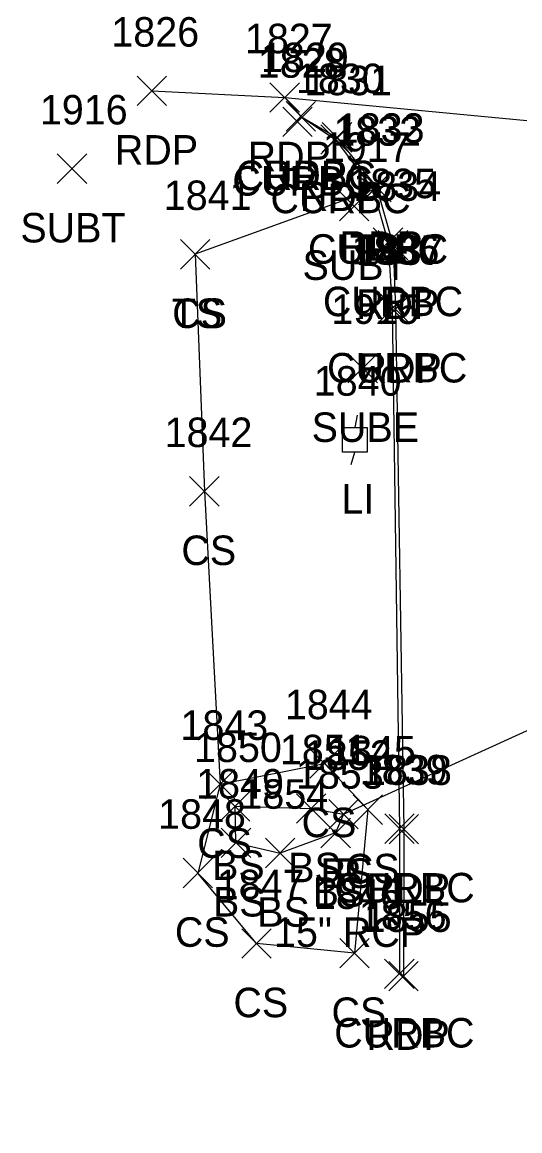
# Model space of a CAD drawing. Extents: x 1462089 to 1464015, y 730534 to 736144.
# Drawn here: x 1462879.2 to 1462912.9, y 734929.7 to 735004.8 of the extents above; entities that cross this region are included whole.
import ezdxf

# ---------------------------------------------------------------- set-up
doc = ezdxf.new("R2010")
doc.units = 0
for name, color, linetype in [('D_A', 7, 'Continuous'), ('D_C', 7, 'Continuous'), ('D_I', 7, 'Continuous'), ('D_TIC', 7, 'Continuous'), ('DCP', 7, 'Continuous'), ('L_A', 7, 'Continuous'), ('L_I', 7, 'Continuous'), ('L_TIC', 7, 'Continuous'), ('LELB', 7, 'Continuous'), ('P_A', 7, 'Continuous'), ('P_I', 7, 'Continuous'), ('P_TIC', 7, 'Continuous'), ('PET', 7, 'Continuous'), ('R_A', 7, 'Continuous'), ('R_I', 7, 'Continuous'), ('R_TIC', 7, 'Continuous'), ('RC', 7, 'Continuous'), ('U_A', 7, 'Continuous'), ('U_I', 7, 'Continuous'), ('U_TIC', 7, 'Continuous'), ('ULP', 7, 'Continuous')]:
    doc.layers.add(name, color=color, linetype=linetype)

msp = doc.modelspace()

# ---------------------------------------------------------------- linework, layer by layer
at = {"layer": 'D_TIC'}
for points in [[(1462899.982, 734950.137), (1462901.982, 734952.137)], [(1462901.982, 734950.137), (1462899.982, 734952.137)]]:
    msp.add_lwpolyline(points, dxfattribs=at)
at = {"layer": 'DCP'}
msp.add_lwpolyline([(1462900.982, 734951.137), (1462945.828, 734971.561)], dxfattribs=at)
at = {"layer": 'L_TIC'}
for points in [[(1462901.983, 734992.46), (1462903.983, 734994.46)], [(1462903.983, 734992.46), (1462901.983, 734994.46)], [(1462889.919, 734988.102), (1462891.919, 734990.102)], [(1462891.919, 734988.102), (1462889.919, 734990.102)], [(1462889.919, 734988.102), (1462891.919, 734990.102)], [(1462891.919, 734988.102), (1462889.919, 734990.102)], [(1462890.542, 734972.031), (1462892.542, 734974.031)], [(1462892.542, 734972.031), (1462890.542, 734974.031)], [(1462898.695, 734953.579), (1462900.695, 734955.579)], [(1462900.695, 734953.579), (1462898.695, 734955.579)], [(1462891.616, 734952.175), (1462893.616, 734954.175)], [(1462893.616, 734952.175), (1462891.616, 734954.175)], [(1462891.616, 734952.175), (1462893.616, 734954.175)], [(1462893.616, 734952.175), (1462891.616, 734954.175)], [(1462892.625, 734950.673), (1462894.625, 734952.673)], [(1462894.625, 734950.673), (1462892.625, 734952.673)], [(1462897.789, 734950.522), (1462899.789, 734952.522)], [(1462899.789, 734950.522), (1462897.789, 734952.522)], [(1462899.982, 734950.137), (1462901.982, 734952.137)], [(1462901.982, 734950.137), (1462899.982, 734952.137)], [(1462901.625, 734950.448), (1462903.625, 734952.448)], [(1462903.625, 734950.448), (1462901.625, 734952.448)], [(1462899.442, 734948.866), (1462901.442, 734950.866)], [(1462901.442, 734948.866), (1462899.442, 734950.866)], [(1462892.686, 734948.2), (1462894.686, 734950.2)], [(1462894.686, 734948.2), (1462892.686, 734950.2)], [(1462892.686, 734948.2), (1462894.686, 734950.2)], [(1462894.686, 734948.2), (1462892.686, 734950.2)], [(1462895.681, 734947.505), (1462897.681, 734949.505)], [(1462897.681, 734947.505), (1462895.681, 734949.505)], [(1462895.681, 734947.505), (1462897.681, 734949.505)], [(1462897.681, 734947.505), (1462895.681, 734949.505)], [(1462890.103, 734946.147), (1462892.103, 734948.147)], [(1462892.103, 734946.147), (1462890.103, 734948.147)], [(1462890.103, 734946.147), (1462892.103, 734948.147)], [(1462892.103, 734946.147), (1462890.103, 734948.147)], [(1462894.073, 734941.372), (1462896.073, 734943.372)], [(1462896.073, 734941.372), (1462894.073, 734943.372)], [(1462900.722, 734940.712), (1462902.722, 734942.712)], [(1462902.722, 734940.712), (1462900.722, 734942.712)]]:
    msp.add_lwpolyline(points, dxfattribs=at)
at = {"layer": 'LELB'}
for points in [[(1462902.983, 734993.46), (1462890.919, 734989.102)], [(1462890.919, 734989.102), (1462891.542, 734973.031), (1462892.616, 734953.175), (1462899.695, 734954.579), (1462902.625, 734951.448), (1462901.722, 734941.712), (1462895.073, 734942.372), (1462891.103, 734947.147)], [(1462892.616, 734953.175), (1462891.103, 734947.147)], [(1462893.686, 734949.2), (1462893.625, 734951.673), (1462898.789, 734951.522), (1462900.982, 734951.137), (1462900.442, 734949.866), (1462896.681, 734948.505)], [(1462893.686, 734949.2), (1462896.681, 734948.505)]]:
    msp.add_lwpolyline(points, dxfattribs=at)
at = {"layer": 'P_TIC'}
for points in [[(1462886.986, 734999.181), (1462888.986, 735001.181)], [(1462888.986, 734999.181), (1462886.986, 735001.181)], [(1462895.989, 734998.734), (1462897.989, 735000.734)], [(1462897.989, 734998.734), (1462895.989, 735000.734)], [(1462895.989, 734998.734), (1462897.989, 735000.734)], [(1462897.989, 734998.734), (1462895.989, 735000.734)], [(1462897.085, 734997.453), (1462899.085, 734999.453)], [(1462899.085, 734997.453), (1462897.085, 734999.453)], [(1462899.534, 734996.026), (1462901.534, 734998.026)], [(1462901.534, 734996.026), (1462899.534, 734998.026)], [(1462902.215, 734992.659), (1462904.215, 734994.659)], [(1462904.215, 734992.659), (1462902.215, 734994.659)], [(1462903.333, 734988.722), (1462905.333, 734990.722)], [(1462905.333, 734988.722), (1462903.333, 734990.722)], [(1462903.506, 734984.385), (1462905.506, 734986.385)], [(1462905.506, 734984.385), (1462903.506, 734986.385)], [(1462904.066, 734949.12), (1462906.066, 734951.12)], [(1462906.066, 734949.12), (1462904.066, 734951.12)], [(1462904.047, 734939.154), (1462906.047, 734941.154)], [(1462906.047, 734939.154), (1462904.047, 734941.154)]]:
    msp.add_lwpolyline(points, dxfattribs=at)
at = {"layer": 'PET'}
for points in [[(1462887.986, 735000.181), (1462896.989, 734999.734), (1462921.504, 734997.41), (1462942.797, 734994.694), (1462953.494, 734994.048), (1462984.274, 734990.195), (1463026.29, 734985.411), (1463062.307, 734980.204), (1463112.763, 734970.65), (1463141.534, 734965.09), (1463163.133, 734960.719), (1463175.951, 734956.699), (1463185.663, 734949.178), (1463198.507, 734929.668)], [(1462896.989, 734999.734), (1462898.085, 734998.453), (1462900.534, 734997.026), (1462903.215, 734993.659), (1462904.333, 734989.722), (1462904.506, 734985.385), (1462905.066, 734950.12), (1462905.047, 734940.154)]]:
    msp.add_lwpolyline(points, dxfattribs=at)
at = {"layer": 'R_TIC'}
for points in [[(1462896.856, 734997.077), (1462898.856, 734999.077)], [(1462898.856, 734997.077), (1462896.856, 734999.077)], [(1462897.085, 734997.453), (1462899.085, 734999.453)], [(1462899.085, 734997.453), (1462897.085, 734999.453)], [(1462899.443, 734995.887), (1462901.443, 734997.887)], [(1462901.443, 734995.887), (1462899.443, 734997.887)], [(1462901.983, 734992.46), (1462903.983, 734994.46)], [(1462903.983, 734992.46), (1462901.983, 734994.46)], [(1462902.997, 734988.905), (1462904.997, 734990.905)], [(1462904.997, 734988.905), (1462902.997, 734990.905)], [(1462903.276, 734984.409), (1462905.276, 734986.409)], [(1462905.276, 734984.409), (1462903.276, 734986.409)], [(1462903.778, 734949.159), (1462905.778, 734951.159)], [(1462905.778, 734949.159), (1462903.778, 734951.159)], [(1462903.766, 734939.316), (1462905.766, 734941.316)], [(1462905.766, 734939.316), (1462903.766, 734941.316)]]:
    msp.add_lwpolyline(points, dxfattribs=at)
at = {"layer": 'RC'}
msp.add_lwpolyline([(1462897.856, 734998.077), (1462898.085, 734998.453), (1462900.443, 734996.887), (1462902.983, 734993.46), (1462903.997, 734989.905), (1462904.276, 734985.409), (1462904.778, 734950.159), (1462904.766, 734940.316)], dxfattribs=at)
at = {"layer": 'U_TIC'}
for points in [[(1462881.574, 734993.904), (1462883.574, 734995.904)], [(1462883.574, 734993.904), (1462881.574, 734995.904)], [(1462900.702, 734991.364), (1462902.702, 734993.364)], [(1462902.702, 734991.364), (1462900.702, 734993.364)], [(1462901.28, 734980.378), (1462903.28, 734982.378)], [(1462903.28, 734980.378), (1462901.28, 734982.378)]]:
    msp.add_lwpolyline(points, dxfattribs=at)
at = {"layer": 'ULP'}
for p, q in [((1462901.907, 734978.183), (1462901.74, 734977.35)), ((1462900.907, 734975.683), (1462900.907, 734977.35)), ((1462900.907, 734977.35), (1462902.574, 734977.35)), ((1462902.574, 734977.35), (1462902.574, 734975.683)), ((1462901.74, 734976.516), (1462901.74, 734976.516)), ((1462902.574, 734975.683), (1462900.907, 734975.683)), ((1462901.49, 734974.85), (1462901.74, 734975.683))]:
    msp.add_line(p, q, dxfattribs=at)

# ---------------------------------------------------------------- texts
at = {"layer": 'D_A'}
msp.add_text('P', height=2, dxfattribs=at).set_placement((1462900.36, 734946.137))
at = {"layer": 'D_C'}
msp.add_text('15" RCP', height=2, dxfattribs=at).set_placement((1462896.266, 734942.137))
at = {"layer": 'D_I'}
msp.add_text('1852', height=2, dxfattribs=at).set_placement((1462898.289, 734954.137))
at = {"layer": 'L_A'}
for s, p in [('TS', (1462901.392, 734988.46)), ('TS', (1462889.329, 734984.102)), ('CS', (1462889.36, 734984.102)), ('CS', (1462889.983, 734968.031)), ('CS', (1462898.136, 734949.579)), ('CS', (1462891.057, 734948.175)), ('CS', (1462891.057, 734948.175)), ('BS', (1462892.066, 734946.673)), ('BS', (1462897.23, 734946.522)), ('CS', (1462901.066, 734946.448)), ('BS', (1462899.423, 734946.137)), ('BS', (1462898.883, 734944.866)), ('BS', (1462892.127, 734944.2)), ('BS', (1462892.127, 734944.2)), ('BS', (1462895.122, 734943.505)), ('BS', (1462895.122, 734943.505)), ('CS', (1462889.544, 734942.147)), ('CS', (1462889.544, 734942.147)), ('CS', (1462893.514, 734937.372)), ('CS', (1462900.163, 734936.712))]:
    msp.add_text(s, height=2, dxfattribs=at).set_placement(p)
at = {"layer": 'L_I'}
for s, p in [('1832', (1462900.29, 734996.46)), ('1841', (1462888.793, 734992.102)), ('1841', (1462888.793, 734992.102)), ('1842', (1462888.85, 734976.031)), ('1844', (1462897.002, 734957.579)), ('1843', (1462889.924, 734956.175)), ('1843', (1462889.924, 734956.175)), ('1850', (1462890.846, 734954.673)), ('1851', (1462896.663, 734954.522)), ('1852', (1462898.289, 734954.137)), ('1845', (1462899.932, 734954.448)), ('1853', (1462897.749, 734952.866)), ('1849', (1462890.986, 734952.2)), ('1849', (1462890.986, 734952.2)), ('1854', (1462893.988, 734951.505)), ('1854', (1462893.988, 734951.505)), ('1848', (1462888.41, 734950.147)), ('1848', (1462888.41, 734950.147)), ('1847', (1462892.381, 734945.372)), ('1846', (1462898.974, 734944.712))]:
    msp.add_text(s, height=2, dxfattribs=at).set_placement(p)
at = {"layer": 'P_A'}
for p in [(1462885.474, 734995.181), (1462894.477, 734994.734), (1462894.477, 734994.734), (1462895.573, 734993.453), (1462898.022, 734992.026), (1462900.704, 734988.659), (1462901.821, 734984.722), (1462901.995, 734980.385), (1462902.554, 734945.12), (1462902.535, 734935.154)]:
    msp.add_text('RDP', height=2, dxfattribs=at).set_placement(p)
at = {"layer": 'P_I'}
for s, p in [('1826', (1462885.238, 735003.181)), ('1827', (1462894.296, 735002.734)), ('1827', (1462894.296, 735002.734)), ('1829', (1462895.384, 735001.453)), ('1830', (1462897.755, 735000.026)), ('1833', (1462900.523, 734996.659)), ('1834', (1462901.64, 734992.722)), ('1837', (1462901.814, 734988.385)), ('1838', (1462902.373, 734953.12)), ('1855', (1462902.354, 734943.154))]:
    msp.add_text(s, height=2, dxfattribs=at).set_placement(p)
at = {"layer": 'R_A'}
for p in [(1462893.439, 734993.077), (1462893.667, 734993.453), (1462896.025, 734991.887), (1462898.565, 734988.46), (1462899.58, 734984.905), (1462899.859, 734980.409), (1462900.361, 734945.159), (1462900.348, 734935.316)]:
    msp.add_text('CURBC', height=2, dxfattribs=at).set_placement(p)
at = {"layer": 'R_I'}
for s, p in [('1829', (1462895.384, 735001.453)), ('1828', (1462895.163, 735001.077)), ('1831', (1462898.317, 734999.887)), ('1832', (1462900.29, 734996.46)), ('1835', (1462901.304, 734992.905)), ('1836', (1462901.528, 734988.409)), ('1839', (1462902.077, 734953.159)), ('1856', (1462902.018, 734943.316))]:
    msp.add_text(s, height=2, dxfattribs=at).set_placement(p)
at = {"layer": 'U_A'}
for s, p in [('SUBT', (1462879.07, 734989.904)), ('SUBT', (1462898.198, 734987.364)), ('SUBE', (1462898.816, 734976.378)), ('LI', (1462900.843, 734971.516))]:
    msp.add_text(s, height=2, dxfattribs=at).set_placement(p)
at = {"layer": 'U_I'}
for s, p in [('1916', (1462880.393, 734997.904)), ('1917', (1462899.576, 734995.364)), ('1915', (1462900.154, 734984.378)), ('1840', (1462898.961, 734979.516))]:
    msp.add_text(s, height=2, dxfattribs=at).set_placement(p)

doc.saveas('drawing.dxf')
